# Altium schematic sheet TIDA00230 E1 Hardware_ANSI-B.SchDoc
size 431 x 279 mm; Date: Not shown in title block; ApprovedBy: Not shown in title block; CheckedBy: Not shown in title block; Author: Not shown in title block; CompanyName: Not shown in title block; Engineer: Not shown in title block; Organization: Not shown in title block; Address1: Not shown in title block; Address2: Not shown in title block; Address3: Not shown in title block; Address4: Not shown in title block; DocumentNumber: 1; Revision: Use project parameter SCH_Rev; SheetNumber: 1; SheetTotal: 1; PageSetup: Record=PageOptions|CenterHorizontal=True|CenterVertical=True|PrintScale=1.00|XCorrection=1.00|YCorrection=1.00|PrintKind=0|BorderSize=5000000|LeftOffset=0|BottomOffset=0|Orientation=2|PaperLength=1000|PaperWidth=1000|Scale=100|PaperSource=15|PrintQuality=600|MediaType=1|DitherType=10|PaperKind=Letter|PrintScaleMode=1
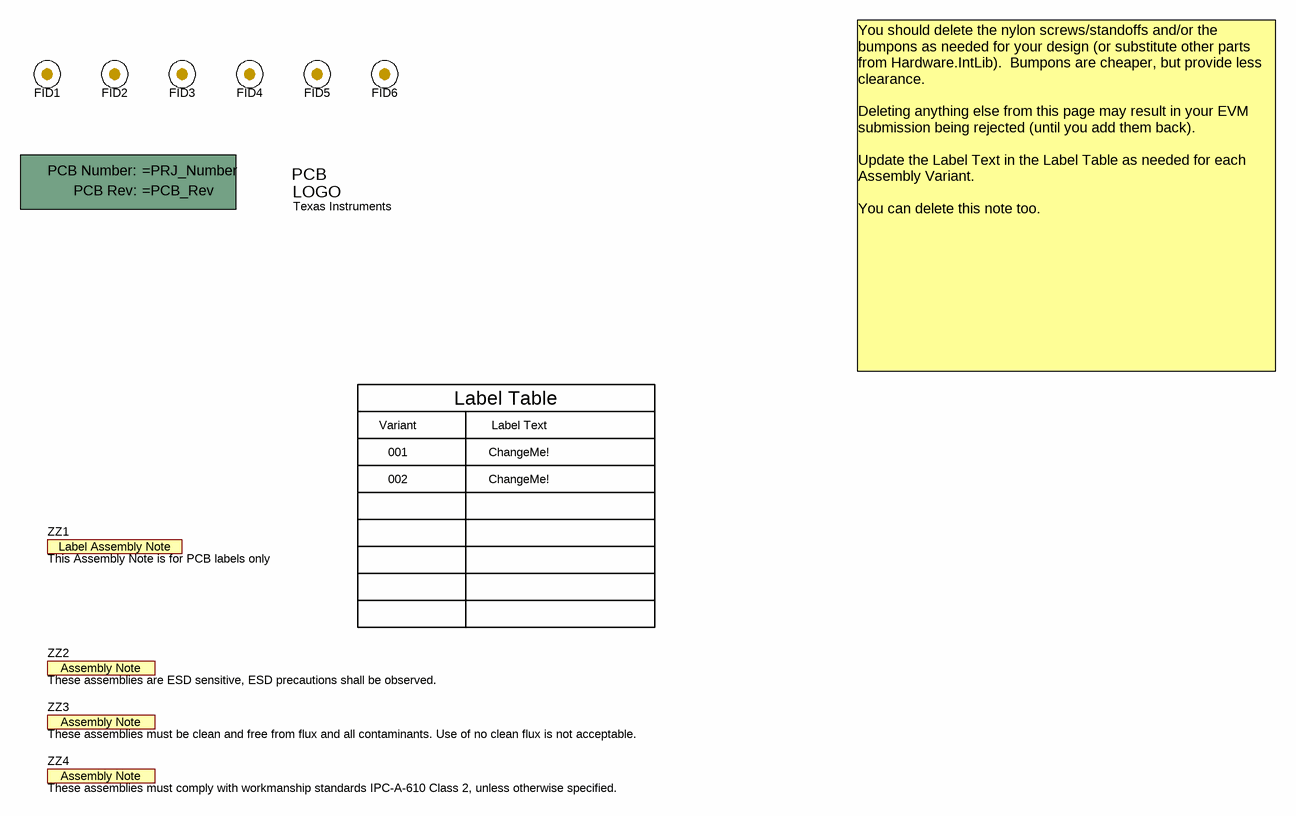
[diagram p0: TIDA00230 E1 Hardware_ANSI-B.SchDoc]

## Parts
!PCB1  Printed Circuit Board  (value not drawn)  (mechanical)
FID1  Fiducial  [Fiducial10-20]  (value not drawn)
FID2  Fiducial  [Fiducial10-20]  (value not drawn)
FID3  Fiducial  [Fiducial10-20]  (value not drawn)
FID4  Fiducial  [Fiducial10-20]  (value not drawn)
FID5  Fiducial  [Fiducial10-20]  (value not drawn)
FID6  Fiducial  [Fiducial10-20]  (value not drawn)
Logo1  Texas Instruments  [TI_Symbol_Overlay_Small]  (no BOM)
ZZ1  This Assembly Note is for PCB labels only  [AssemblyNoteLabel]  (no BOM)
ZZ2  These assemblies are ESD sensitive, ESD precautions shall be observed.  [AssemblyNote]  (no BOM)
ZZ3  These assemblies must be clean and free from flux and all contaminants. Use of no clean flux is not acceptable.  [AssemblyNote]  (no BOM)
ZZ4  These assemblies must comply with workmanship standards IPC-A-610 Class 2, unless otherwise specified.  [AssemblyNote]  (no BOM)

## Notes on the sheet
- Variant
- Label Table
- Label Text
- You should delete the nylon screws/standoffs and/or the bumpons as needed for your design (or substitute other parts from Hardware.IntLib).  Bumpons are cheaper, but provide less clearance.
  Deleting anything else from this page may result in your EVM submission being rejected (until you add them back).
  Update the Label Text in the Label Table as needed for each Assembly Variant.
  You can delete this note too.
- 001
- 002
- ChangeMe!

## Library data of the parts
!PCB1 = PCB: Manufacturer: Any; SymbolCreator: a0412235
FID1-FID6 = Fiducial: Fiducial mark.  There is nothing to buy or mount.; SymbolCreator: codlsc
Logo1 = TI_Logo: Texas Instrument Corporate Signature; SymbolCreator: codlsc
ZZ1 = AssemblyNoteLabel: SymbolCreator: a0412235
ZZ2-ZZ4 = AssemblyNote: SymbolCreator: codlsc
